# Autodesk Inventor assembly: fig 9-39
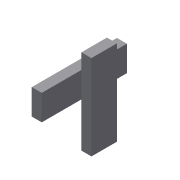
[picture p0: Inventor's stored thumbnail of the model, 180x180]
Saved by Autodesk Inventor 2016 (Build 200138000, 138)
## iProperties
Created: 2013-07
Part Number: fig 9-39
Document SubType Name: Assembly
Designer: CADCIM
Author: CADCIM
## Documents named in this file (2)
- D:\KAVITA\Autodesk Inventor_ 2016 Project_Kavita\Inventor_Part Files\Inventor_2016_Part\c09_Inv_2016\c09_inv_2016_prt\fig 9-39.iam
- D:\KAVITA\Autodesk Inventor_ 2016 Project_Kavita\Inventor_Part Files\Inventor_2016_Part\c09_Inv_2016\c09_inv_2016_prt\12.ipt
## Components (2 placed, 1 different names)
1. 12:1
2. 12:2
